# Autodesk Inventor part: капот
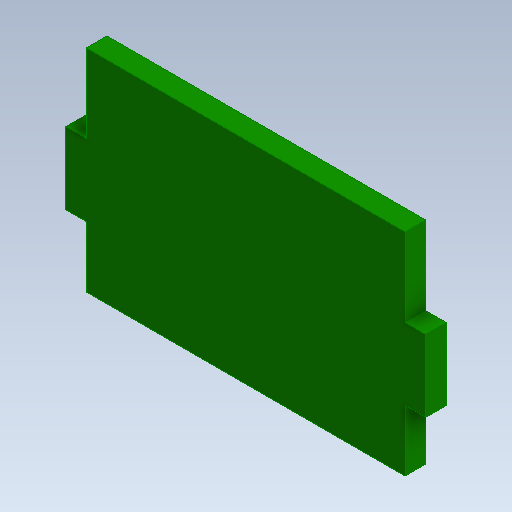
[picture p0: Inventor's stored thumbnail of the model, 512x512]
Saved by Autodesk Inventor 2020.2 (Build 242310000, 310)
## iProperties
Created: 2020-04
Part Number: капот
Material: Типовые
Document SubType Name: Modeling
Designer: Алексей
Density: 1 g/cm^3
Appearance: По умолчанию
Author: Алексей
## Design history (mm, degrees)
sketch "Эскиз1"
  geometry: L1 (14, 14)-(14, 0) reference; L2 (10, 14)-(14, 14) reference; L3 (0, 0)-(10, 14) reference; L4 (0, 0)-(14, 0) reference; L5 (-52, 14)-(-52, 0) reference; L6 (-56, 14)-(-52, 14) reference; L7 (-56, 0)-(-56, 14) reference; L8 (-56, 0)-(-52, 0) reference; L9 (-52, -11.863)-(-56, -11.863) reference; L10 (-52, 29.277)-(-56, 29.277) reference; L11 (14, 29.277)-(10, 29.277) reference; L12 (14, -11.863)-(10, -11.863) reference; L13 (10, 29.277)-(-52, 29.277); L14 (-52, 29.277)-(-52, -11.863); L15 (-52, -11.863)-(10, -11.863); L16 (10, -11.863)-(10, 29.277); 4 further points
  constraints: 8 end point, 2 parallel, 1 horizontal, 1 perpendicular
extrude "Выдавливание1" new body sketch "Эскиз1" distance "d0" = 4; taper "d1" = 0 deg
node "Твердое тело1"
node "Ссылка1"
node "Ссылка2"
node "Ссылка3"
node "Ссылка4"
node "Ссылка5"
node "Ссылка6"
